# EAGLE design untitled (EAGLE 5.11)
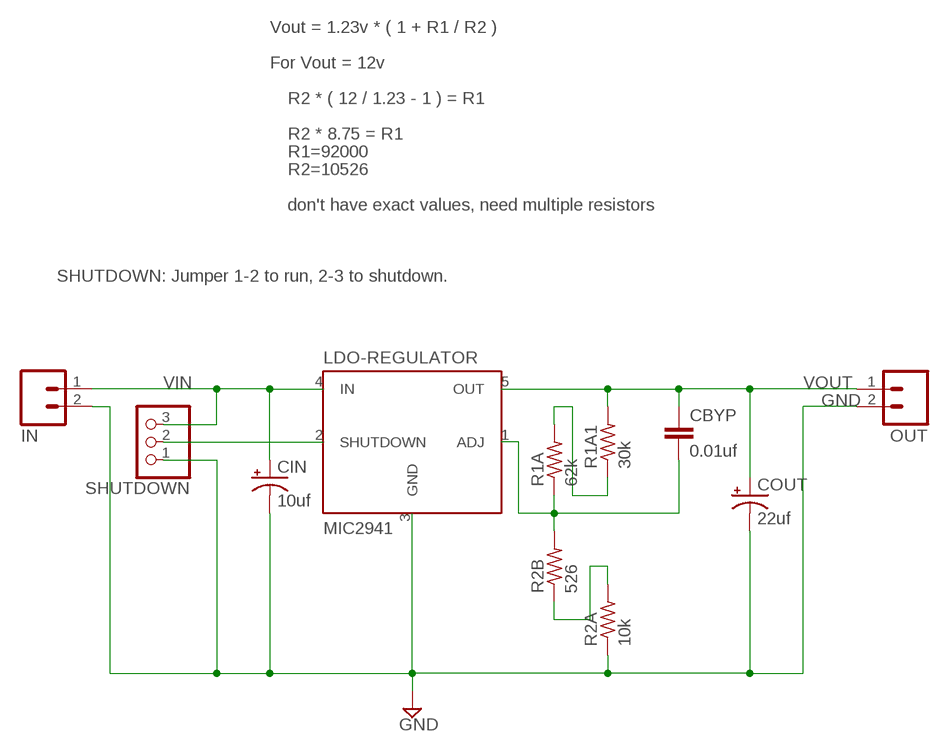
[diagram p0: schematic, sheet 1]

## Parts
CBYP  0.01uf  C-EU025-050X050  [C025-050X050]
CIN  10uf  CPOL-USE2-5  [E2-5]
COUT  22uf  CPOL-USE2-5  [E2-5]
IN  M02PTH  [1X02]
LDO-REGULATOR  MIC2941  [TO-220-5]
OUT  M02PTH  [1X02]
R1A  62k  R-US_0204/7  [0204/7]
R1A1  30k  R-US_0204/7  [0204/7]
R2A  10k  R-US_0207/10  [0207/10]
R2B  526  R-US_0204/5  [0204/5]
SHUTDOWN  PINHD-1X3  [1X03]

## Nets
GND: CIN.- COUT.- IN.2 LDO-REGULATOR.3(GND) OUT.2 R2A.1 SHUTDOWN.1
N$1: R2A.2 R2B.1
N$2: CBYP.2 LDO-REGULATOR.1(ADJ) R1A.1 R2B.2
N$3: R1A1.1 R1A.2
N$4: LDO-REGULATOR.2(SHUTDOWN) SHUTDOWN.2
VIN: CIN.+ IN.1 LDO-REGULATOR.4(IN) SHUTDOWN.3
VOUT: CBYP.1 COUT.+ LDO-REGULATOR.5(OUT) OUT.1 R1A1.2

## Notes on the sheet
- Vout = 1.23v * ( 1 + R1 / R2 )
- For Vout = 12v
- R2 * ( 12 / 1.23 - 1 ) = R1
- R2 * 8.75 = R1
- R1=92000
- R2=10526
- don't have exact values, need multiple resistors
- SHUTDOWN: Jumper 1-2 to run, 2-3 to shutdown.

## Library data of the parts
CBYP = rcl:C-EU: CAPACITOR, European symbol
CIN COUT = rcl:CPOL-US: POLARIZED CAPACITOR, American symbol
IN OUT = SparkFun:M02: Header 2
LDO-REGULATOR = trl:MIC2941
R1A R1A1 R2A R2B = resistor:R-US_: RESISTOR, American symbol
SHUTDOWN = pinhead:PINHD-1X3: PIN HEADER

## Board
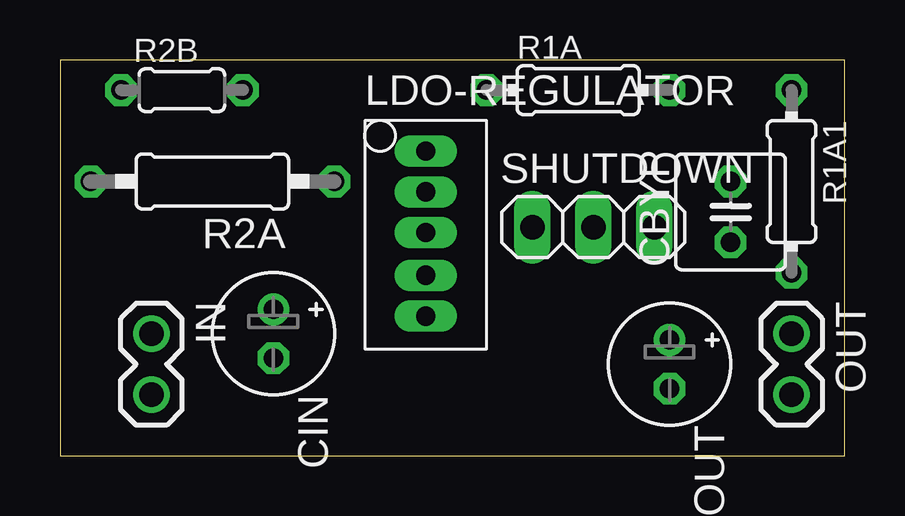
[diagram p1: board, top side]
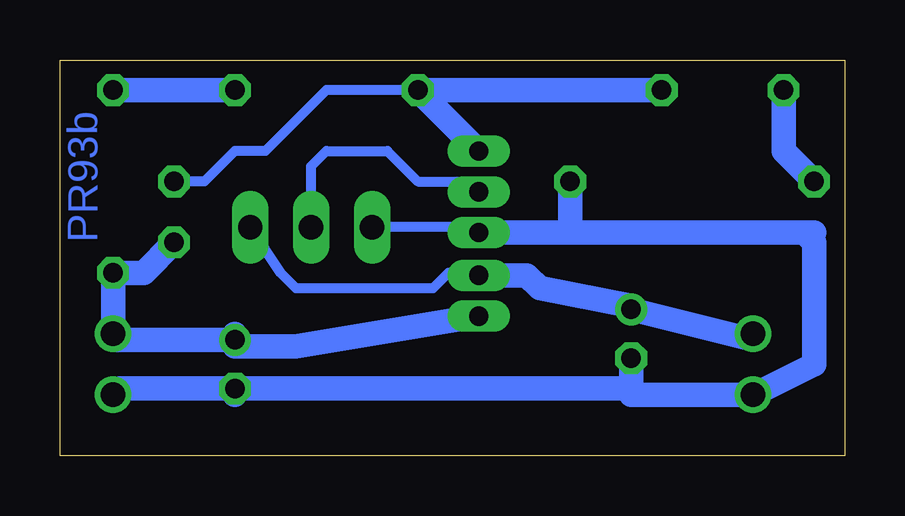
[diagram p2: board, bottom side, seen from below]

Size 32.69 x 16.5 mm. Coordinates in mm from the lower left corner, seen from the top.
Outline: 0,0 32.69,0 32.69,16.5 0,16.5 0,0
Copper layers (1*16): Top 0.035mm / dielectric 1.5mm / Bottom 0.035mm
Design rules "default": minimum track width 10mil, minimum drill 24mil, track to track 8mil, track to pad 8mil, pad to pad 8mil, via to via 8mil, smd to smd 8mil, copper to edge 40mil, drill to drill 8mil, minimum pad ring 10mil, minimum via ring 8mil, stop-mask expansion 4mil, vias tented up to drill 0mil, thermal gap 10mil

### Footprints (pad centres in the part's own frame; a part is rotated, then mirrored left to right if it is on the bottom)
C025-050X050 = drill 0.813 octagon: 1 -1.27,0; 2 1.27,0
E2-5 = drill 0.813 pad 1.27 round: + -1.016,0 | drill 0.813 pad 1.27 octagon: - 1.016,0
1X02 = drill 1.016 round: 1 0,0; 2 2.54,0
TO-220-5 = drill 0.8 long: 1 -3.81,0; 2 -2.108,0; 3 -0.406,0; 4 1.372,0; 5 3.073,0
0204/7 = drill 0.813 octagon: 1 -3.81,0; 2 3.81,0
0207/10 = drill 0.813 octagon: 1 -5.08,0; 2 5.08,0
0204/5 = drill 0.813 octagon: 1 -2.54,0; 2 2.54,0
1X03 = drill 1.016 long: 1 -2.54,0; 2 0,0; 3 2.54,0

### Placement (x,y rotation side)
CBYP  27.94,10.16 90 top
CIN  8.89,5.08 270 top
COUT  25.4,3.81 270 top
IN  3.81,5.08 270 top
LDO-REGULATOR  15.24,8.89 270 top
OUT  30.48,5.08 270 top
R1A  21.59,15.24 0 top
R1A1  30.48,11.43 270 top
R2A  6.35,11.43 180 top
R2B  5.08,15.24 0 top
SHUTDOWN  22.23,9.53 0 top

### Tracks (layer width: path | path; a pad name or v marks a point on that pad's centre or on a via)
GND
  Bottom 0.406: SHUTDOWN.1 15.47,9.53 LDO-REGULATOR.3
  Bottom 1.016: 1.68,9.3 1.27,9.3 | 1.68,9.3 11.43,9.3 | 11.43,9.3 LDO-REGULATOR.3 | 1.68,9.3 1.27,8.89 1.27,3.81 IN.2 8.89,2.54 8.89,2.79 | COUT.- 25.4,2.54 | COUT.- 30.23,2.79 OUT.2 | 8.89,2.79 CIN.- | 11.43,9.3 R2A.1 | 8.89,2.79 COUT.-
N$1
  Bottom 1.016: R2B.1 2.54,12.7 R2A.2
N$2
  Bottom 0.406: CBYP.2 26.67,11.43 25.4,12.7 24.13,12.7 21.59,15.24 R1A.1
  Bottom 1.016: R2B.2 R1A.1 LDO-REGULATOR.1
N$3
  Bottom 1.016: R1A.2 R1A1.1
N$4
  Bottom 0.406: SHUTDOWN.2 22.23,12.06 21.59,12.7 19.05,12.7 17.78,11.43 15.67,11.43 LDO-REGULATOR.2
VIN
  Bottom 0.406: SHUTDOWN.3 23.5,7.62 22.86,6.99 17.14,6.99 16.51,7.62 15.34,7.62 LDO-REGULATOR.4
  Bottom 1.016: LDO-REGULATOR.4 13.23,7.52 12.7,6.99 8.89,6.25 CIN.+ 3.81,4.83 IN.1
VOUT
  Bottom 1.016: LDO-REGULATOR.5 22.86,4.55 25.4,4.55 COUT.+ | COUT.+ 25.4,5.08 | COUT.+ 30.48,4.83 OUT.1 R1A1.2 29.21,7.62 CBYP.1

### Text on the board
Bottom: PR93b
